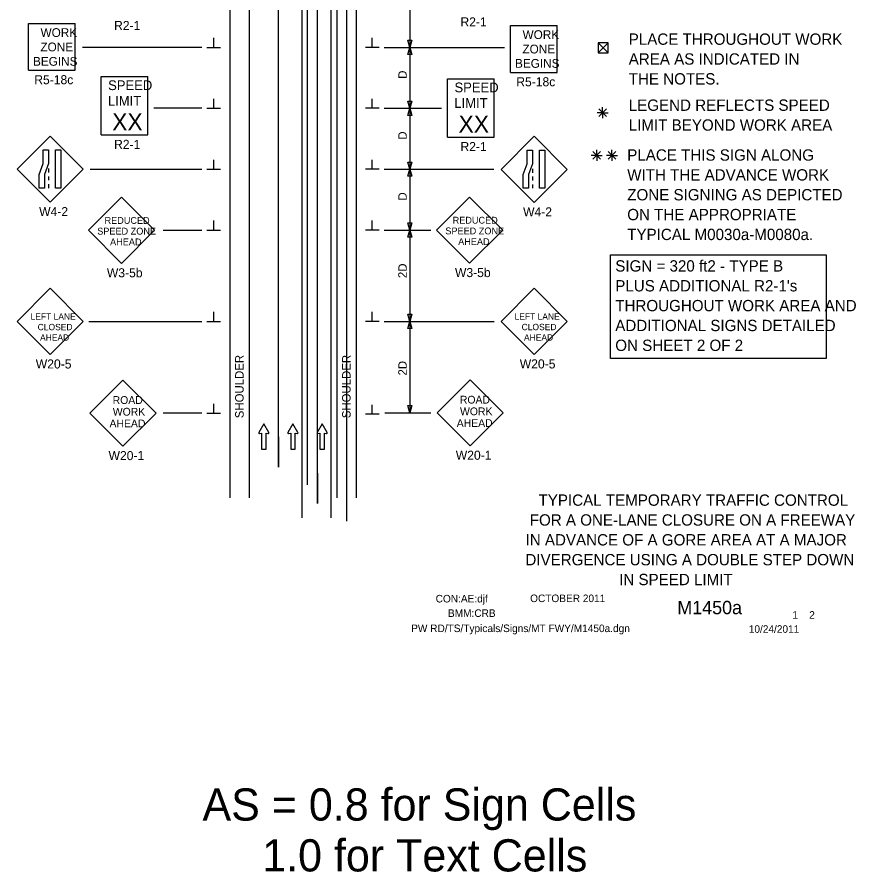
# Model space of a CAD drawing. Extents: x 16729 to 18464, y 5737 to 6974.
# Drawn here: x 16747 to 17436, y 5737 to 6439 of the extents above; entities that cross this region are included whole.
import ezdxf

# ---------------------------------------------------------------- set-up
doc = ezdxf.new("R2010")
doc.units = 0
for name, color, linetype in [('ALI_LEGAL_EX', 7, 'Continuous'), ('BORDER', 7, 'Continuous'), ('BORDER_SIGNAL_WO', 7, 'Continuous'), ('MT_SCRATCH_LEVEL_E', 7, 'Continuous'), ('PAVT_EDGE_EX', 7, 'Continuous'), ('TRAFFIC_SIGNS_PR', 7, 'Continuous'), ('TYPICAL_TEXT_DIMEN_EX', 7, 'Continuous'), ('TYPICAL_TEXT_DIMEN_PR', 7, 'Continuous')]:
    doc.layers.add(name, color=color, linetype=linetype)

msp = doc.modelspace()

# ---------------------------------------------------------------- linework, layer by layer
at = {"layer": 'ALI_LEGAL_EX'}
for p, q in [((16980.68, 6974.12), (16980.68, 6155.98)), ((17004.68, 6974.12), (17004.68, 6155.98)), ((16980.68, 6891.53), (16980.68, 6027.61)), ((17004.68, 6891.53), (17004.68, 6027.61)), ((16961.51, 6069.17), (16961.51, 6569.52)), ((16985.51, 6054.68), (16985.51, 6555.03)), ((16993.65, 6039.29), (16993.65, 6539.64)), ((17017.65, 6024.8), (17017.65, 6525.15))]:
    msp.add_line(p, q, dxfattribs=at)
for points in [[(16961.51, 6369.17), (16961.51, 6394.17)], [(16985.51, 6369.17), (16985.51, 6394.17)], [(16961.51, 6269.17), (16961.51, 6294.17)], [(16985.51, 6269.17), (16985.51, 6294.17)], [(16961.51, 6169.17), (16961.51, 6194.17)], [(16985.51, 6169.17), (16985.51, 6194.17)], [(16961.51, 6094.17), (16961.51, 6069.17)], [(16961.51, 6069.17), (16961.51, 6094.17)], [(16985.51, 6069.17), (16985.51, 6094.17)], [(16993.65, 6064.29), (16993.65, 6039.29)]]:
    msp.add_lwpolyline(points, dxfattribs=at)
at = {"layer": 'MT_SCRATCH_LEVEL_E'}
for p, q in [((16949.53, 6104.79), (16945.42, 6097.55)), ((16953.67, 6097.55), (16949.53, 6104.79)), ((16973.43, 6104.79), (16969.32, 6097.55)), ((16977.58, 6097.55), (16973.43, 6104.79)), ((16997.48, 6104.79), (16993.37, 6097.55)), ((17001.63, 6097.55), (16997.48, 6104.79)), ((16945.9, 6096.87), (16947.67, 6097.18)), ((16947.67, 6097.18), (16947.67, 6083.93)), ((16951.42, 6083.93), (16951.42, 6097.18)), ((16951.42, 6097.18), (16953.19, 6096.87)), ((16969.8, 6096.87), (16971.58, 6097.18)), ((16971.58, 6097.18), (16971.58, 6083.93)), ((16975.32, 6083.93), (16975.32, 6097.18)), ((16975.32, 6097.18), (16977.1, 6096.87)), ((16993.85, 6096.87), (16995.63, 6097.18)), ((16995.63, 6097.18), (16995.63, 6083.93)), ((16999.37, 6083.93), (16999.37, 6097.18)), ((16999.37, 6097.18), (17001.15, 6096.87)), ((16947.67, 6083.93), (16951.42, 6083.93)), ((16971.58, 6083.93), (16975.32, 6083.93)), ((16995.63, 6083.93), (16999.37, 6083.93))]:
    msp.add_line(p, q, dxfattribs=at)
for centre, start, end in [((16945.82, 6097.33), 150.42484, 279.96381), ((16953.26, 6097.33), 260.03619, 29.77312), ((16969.73, 6097.33), 150.42484, 279.96381), ((16977.17, 6097.33), 260.03619, 29.77312), ((16993.78, 6097.33), 150.42484, 279.96381), ((17001.22, 6097.33), 260.03619, 29.77312)]:
    msp.add_arc(centre, 0.463, start, end, dxfattribs=at)
at = {"layer": 'PAVT_EDGE_EX'}
for p, q in [((16921.51, 6569.52), (16921.51, 6043.9)), ((16937.51, 6569.52), (16937.51, 6043.9)), ((17009.51, 6569.52), (17009.51, 6043.9)), ((17025.51, 6569.52), (17025.51, 6043.9))]:
    msp.add_line(p, q, dxfattribs=at)
at = {"layer": 'TRAFFIC_SIGNS_PR'}
for p, q in [((16756.1, 6395.03), (16756.1, 6433.43)), ((16756.1, 6433.43), (16794.5, 6433.43)), ((16794.5, 6395.03), (16794.5, 6433.43)), ((17152.09, 6393.34), (17152.09, 6431.74)), ((17152.09, 6431.74), (17190.49, 6431.74)), ((17190.49, 6393.34), (17190.49, 6431.74)), ((16756.1, 6395.03), (16794.5, 6395.03)), ((16815.83, 6389.93), (16854.23, 6389.93)), ((16815.83, 6341.93), (16815.83, 6389.93)), ((16854.23, 6341.93), (16854.23, 6389.93)), ((17100.39, 6388.13), (17138.79, 6388.13)), ((17100.39, 6340.13), (17100.39, 6388.13)), ((17138.79, 6340.13), (17138.79, 6388.13)), ((17152.09, 6393.34), (17190.49, 6393.34)), ((16773.97, 6341.03), (16746.82, 6313.87)), ((16801.12, 6313.87), (16773.97, 6341.03)), ((16815.83, 6341.93), (16854.23, 6341.93)), ((17100.39, 6340.13), (17138.79, 6340.13)), ((17171.57, 6340.82), (17144.41, 6313.66)), ((17198.72, 6313.66), (17171.57, 6340.82)), ((16746.82, 6313.87), (16773.97, 6286.72)), ((16772.72, 6314.36), (16772.72, 6311.16)), ((16773.97, 6286.72), (16801.12, 6313.87)), ((17144.41, 6313.66), (17171.57, 6286.51)), ((17170.32, 6314.15), (17170.32, 6310.95)), ((17171.57, 6286.51), (17198.72, 6313.66)), ((16772.72, 6307.96), (16772.72, 6304.76)), ((17170.32, 6307.75), (17170.32, 6304.55)), ((16772.72, 6301.56), (16772.72, 6298.36)), ((17170.32, 6301.35), (17170.32, 6298.15)), ((16832.62, 6290.78), (16805.47, 6263.63)), ((16859.78, 6263.63), (16832.62, 6290.78)), ((17118.61, 6290.98), (17091.45, 6263.83)), ((17145.76, 6263.83), (17118.61, 6290.98)), ((16805.47, 6263.63), (16832.62, 6236.48)), ((16832.62, 6236.48), (16859.78, 6263.63)), ((17091.45, 6263.83), (17118.61, 6236.68)), ((17118.61, 6236.68), (17145.76, 6263.83)), ((16774.02, 6216), (16746.83, 6188.81)), ((16801.21, 6188.81), (16774.02, 6216)), ((17171.61, 6216.04), (17144.42, 6188.85)), ((17198.8, 6188.85), (17171.61, 6216.04)), ((16746.83, 6188.81), (16774.02, 6161.63)), ((16774.02, 6161.63), (16801.21, 6188.81)), ((17144.42, 6188.85), (17171.61, 6161.67)), ((17171.61, 6161.67), (17198.8, 6188.85)), ((16833.79, 6140.66), (16806.64, 6113.51)), ((16860.95, 6113.51), (16833.79, 6140.66)), ((17119.05, 6140.97), (17091.89, 6113.82)), ((17146.2, 6113.82), (17119.05, 6140.97)), ((16806.64, 6113.51), (16833.79, 6086.36)), ((16833.79, 6086.36), (16860.95, 6113.51)), ((17091.89, 6113.82), (17119.05, 6086.67)), ((17119.05, 6086.67), (17146.2, 6113.82))]:
    msp.add_line(p, q, dxfattribs=at)
for points in [[(16772.72, 6329.61), (16772.72, 6318.43), (16769.38, 6309.55), (16769.38, 6298.36), (16764.89, 6298.36), (16764.89, 6309.55), (16768.23, 6318.43), (16768.23, 6329.61)], [(16782.86, 6329.61), (16782.86, 6298.36), (16778.37, 6298.36), (16778.37, 6329.61)], [(17170.32, 6329.4), (17170.32, 6318.22), (17166.98, 6309.34), (17166.98, 6298.15), (17162.48, 6298.15), (17162.48, 6309.34), (17165.83, 6318.22), (17165.83, 6329.4)], [(17180.46, 6329.4), (17180.46, 6298.15), (17175.96, 6298.15), (17175.96, 6329.4)]]:
    msp.add_lwpolyline(points, close=True, dxfattribs=at)
at = {"layer": 'TYPICAL_TEXT_DIMEN_EX'}
msp.add_lwpolyline([(17234.19, 6243.59), (17411.46, 6243.59), (17411.46, 6158.27), (17234.19, 6158.27)], close=True, dxfattribs=at)
at = {"layer": 'TYPICAL_TEXT_DIMEN_PR'}
for p, q in [((17069.51, 6463.85), (17069.51, 6413.85)), ((16908.39, 6413.85), (16908.39, 6421.64)), ((17038.64, 6413.85), (17038.64, 6421.64)), ((17069.51, 6413.85), (17067.94, 6419.72)), ((17067.94, 6419.72), (17069.51, 6419.72)), ((17069.51, 6419.72), (17071.08, 6419.72)), ((17071.08, 6419.72), (17069.51, 6413.85)), ((17224.29, 6417.48), (17232.29, 6409.48)), ((17224.29, 6409.48), (17232.29, 6417.48)), ((16898.51, 6413.85), (16800.46, 6413.85)), ((16902.76, 6413.85), (16914.01, 6413.85)), ((17044.26, 6413.85), (17033.01, 6413.85)), ((17048.51, 6413.85), (17147.12, 6413.85)), ((17067.94, 6407.99), (17069.51, 6413.85)), ((17069.51, 6413.85), (17069.51, 6363.85)), ((17069.51, 6413.85), (17071.08, 6407.99)), ((17069.51, 6407.99), (17067.94, 6407.99)), ((17071.08, 6407.99), (17069.51, 6407.99)), ((16908.39, 6363.85), (16908.39, 6371.64)), ((17038.64, 6363.85), (17038.64, 6371.64)), ((17069.51, 6363.85), (17067.94, 6369.72)), ((17067.94, 6369.72), (17069.51, 6369.72)), ((17069.51, 6369.72), (17071.08, 6369.72)), ((17071.08, 6369.72), (17069.51, 6363.85)), ((16898.51, 6363.85), (16859.17, 6363.85)), ((16902.76, 6363.85), (16914.01, 6363.85)), ((17044.26, 6363.85), (17033.01, 6363.85)), ((17048.51, 6363.85), (17095.59, 6363.85)), ((17067.94, 6357.99), (17069.51, 6363.85)), ((17069.51, 6363.85), (17069.51, 6313.85)), ((17069.51, 6363.85), (17071.08, 6357.99)), ((17227.85, 6360.22), (17223.32, 6360.22)), ((17224.66, 6363.4), (17231.04, 6357.03)), ((17231.04, 6363.4), (17224.66, 6357.03)), ((17227.85, 6360.22), (17227.85, 6364.67)), ((17227.85, 6360.22), (17231.04, 6360.22)), ((17227.85, 6360.22), (17232.33, 6360.22)), ((17227.85, 6360.22), (17227.85, 6355.72)), ((17069.51, 6357.99), (17067.94, 6357.99)), ((17071.08, 6357.99), (17069.51, 6357.99)), ((17222.99, 6325.16), (17218.46, 6325.16)), ((17219.8, 6328.35), (17226.18, 6321.97)), ((17226.18, 6328.35), (17219.8, 6321.97)), ((17222.99, 6325.16), (17222.99, 6329.61)), ((17222.99, 6325.16), (17226.18, 6325.16)), ((17222.99, 6325.16), (17227.47, 6325.16)), ((17222.99, 6325.16), (17222.99, 6320.66)), ((17235.54, 6325.16), (17231.01, 6325.16)), ((17238.73, 6328.35), (17232.35, 6321.97)), ((17232.36, 6328.35), (17238.73, 6321.97)), ((17235.54, 6325.16), (17235.54, 6329.61)), ((17235.54, 6325.16), (17238.73, 6325.16)), ((17235.54, 6325.16), (17240.02, 6325.16)), ((17235.54, 6325.16), (17235.54, 6320.66)), ((16908.39, 6313.85), (16908.39, 6321.64)), ((17038.64, 6313.85), (17038.64, 6321.64)), ((17069.51, 6313.85), (17067.94, 6319.72)), ((17067.94, 6319.72), (17069.51, 6319.72)), ((17069.51, 6319.72), (17071.08, 6319.72)), ((17071.08, 6319.72), (17069.51, 6313.85)), ((16806.92, 6313.85), (16898.51, 6313.85)), ((16902.76, 6313.85), (16914.01, 6313.85)), ((17044.26, 6313.85), (17033.01, 6313.85)), ((17048.51, 6313.85), (17138.52, 6313.85)), ((17067.94, 6307.99), (17069.51, 6313.85)), ((17069.51, 6313.85), (17069.51, 6263.85)), ((17069.51, 6313.85), (17071.08, 6307.99)), ((17069.51, 6307.99), (17067.94, 6307.99)), ((17071.08, 6307.99), (17069.51, 6307.99)), ((16908.39, 6263.85), (16908.39, 6271.64)), ((17038.64, 6263.85), (17038.64, 6271.64)), ((17069.51, 6263.85), (17067.94, 6269.72)), ((17067.94, 6269.72), (17069.51, 6269.72)), ((17069.51, 6269.72), (17071.08, 6269.72)), ((17071.08, 6269.72), (17069.51, 6263.85)), ((16866.87, 6263.85), (16898.51, 6263.85)), ((16902.76, 6263.85), (16914.01, 6263.85)), ((17044.26, 6263.85), (17033.01, 6263.85)), ((17048.51, 6263.85), (17086.73, 6263.85)), ((17067.94, 6257.99), (17069.51, 6263.85)), ((17069.51, 6263.85), (17069.51, 6188.85)), ((17069.51, 6263.85), (17071.08, 6257.99)), ((17069.51, 6257.99), (17067.94, 6257.99)), ((17071.08, 6257.99), (17069.51, 6257.99)), ((16908.39, 6188.85), (16908.39, 6196.64)), ((17038.64, 6188.85), (17038.64, 6196.64)), ((17069.51, 6188.85), (17067.94, 6194.72)), ((17067.94, 6194.72), (17069.51, 6194.72)), ((17069.51, 6194.72), (17071.08, 6194.72)), ((17071.08, 6194.72), (17069.51, 6188.85)), ((16805.63, 6188.85), (16898.51, 6188.85)), ((16902.76, 6188.85), (16914.01, 6188.85)), ((17044.26, 6188.85), (17033.01, 6188.85)), ((17048.51, 6188.85), (17138.85, 6188.85)), ((17067.94, 6182.99), (17069.51, 6188.85)), ((17069.51, 6188.85), (17069.51, 6113.85)), ((17069.51, 6188.85), (17071.08, 6182.99)), ((17069.51, 6182.99), (17067.94, 6182.99)), ((17071.08, 6182.99), (17069.51, 6182.99)), ((16908.39, 6113.41), (16908.39, 6121.19)), ((17038.64, 6112.64), (17038.64, 6120.42)), ((17069.51, 6113.85), (17067.94, 6119.72)), ((17067.94, 6119.72), (17069.51, 6119.72)), ((17069.51, 6119.72), (17071.08, 6119.72)), ((17071.08, 6119.72), (17069.51, 6113.85)), ((16898.51, 6113.41), (16866.78, 6113.41)), ((16902.76, 6113.41), (16914.01, 6113.41)), ((17044.26, 6112.64), (17033.01, 6112.64)), ((17049.01, 6113.85), (17086.84, 6113.85))]:
    msp.add_line(p, q, dxfattribs=at)
msp.add_lwpolyline([(17224.29, 6417.48), (17224.29, 6409.48), (17232.29, 6409.48), (17232.29, 6417.48)], close=True, dxfattribs=at)

# ---------------------------------------------------------------- texts
at = {"layer": 'BORDER'}
for s, p in [('TYPICAL TEMPORARY TRAFFIC CONTROL', (17175.21, 6037.44)), ('FOR A ONE-LANE CLOSURE ON A FREEWAY', (17167.99, 6021.14)), ('IN ADVANCE OF A GORE AREA AT A MAJOR', (17164.54, 6004.84)), ('DIVERGENCE USING A DOUBLE STEP DOWN ', (17164.42, 5988.54)), ('IN SPEED LIMIT', (17241.42, 5972.24))]:
    msp.add_text(s, height=9.3, dxfattribs=at).set_placement(p)
at = {"layer": 'BORDER_SIGNAL_WO'}
for s, height, p in [('CON:AE:djf  ', 6.2, (17090.69, 5958.06)), ('    OCTOBER 2011    ', 6.2, (17159.08, 5958.34)), ('    M1450a   ', 11, (17272.86, 5948.38)), ('BMM:CRB   ', 6.2, (17100.81, 5946.17)), (' 1    2 ', 6.2, (17381.45, 5944.7)), ('PW RD/TS/Typicals/Signs/MT FWY/M1450a.dgn      ', 6.2, (17070.55, 5933.71)), ('10/24/2011    ', 6.2, (17347.93, 5933.13)), ('AS = 0.8 for Sign Cells', 26.4241, (16899.12, 5778.94)), ('     1.0 for Text Cells', 26.4241, (16899.12, 5737.16))]:
    msp.add_text(s, height=height, dxfattribs=at).set_placement(p)
at = {"layer": 'TRAFFIC_SIGNS_PR'}
for s, height, p in [('R2-1', 7.44, (17111.07, 6431.07)), ('R2-1', 7.44, (16826.51, 6428.11)), ('WORK', 7.217, (16766.1, 6422.4)), ('WORK', 7.217, (17162.09, 6420.71)), ('ZONE', 7.217, (16765.98, 6410.59)), ('ZONE', 7.217, (17161.97, 6408.9)), ('BEGINS', 7.217, (16759.91, 6398.78)), ('BEGINS', 7.217, (17155.9, 6397.09)), ('R5-18c', 7.44, (16760.91, 6383.59)), ('R5-18c', 7.44, (17156.9, 6381.9)), ('SPEED', 8, (16821.6, 6378.79)), ('SPEED', 8, (17106.16, 6376.99)), ('LIMIT', 8, (16821.44, 6365.99)), ('LIMIT', 8, (17106, 6364.19)), ('XX', 14.031, (16824.94, 6345.69)), ('XX', 14.031, (17109.5, 6343.88)), ('R2-1', 7.44, (16826.51, 6330.49)), ('R2-1', 7.44, (17111.07, 6328.69)), ('W4-2', 7.44, (16764.93, 6275.28)), ('W4-2', 7.44, (17162.52, 6275.07)), ('REDUCED', 5.6, (16818.68, 6268.94)), ('REDUCED', 5.6, (17104.67, 6269.14)), ('SPEED ZONE', 5.6, (16812.67, 6260.14)), ('SPEED ZONE', 5.6, (17098.66, 6260.34)), ('AHEAD', 5.6, (16823.23, 6251.34)), ('AHEAD', 5.6, (17109.22, 6251.54)), ('W3-5b', 7.44, (16820.58, 6225.04)), ('W3-5b', 7.44, (17106.56, 6225.24)), ('LEFT LANE', 5.206, (16757.88, 6190.21)), ('LEFT LANE', 5.206, (17155.47, 6190.25)), ('CLOSED', 5.206, (16763.72, 6181.6)), ('CLOSED', 5.206, (17161.31, 6181.64)), ('AHEAD', 5.206, (16765.67, 6172.99)), ('AHEAD', 5.206, (17163.26, 6173.03)), ('W20-5', 7.449, (16762.18, 6150.17)), ('W20-5', 7.449, (17159.77, 6150.21)), ('ROAD', 6.4, (16825.34, 6121.05)), ('ROAD', 6.4, (17110.59, 6121.36)), ('WORK', 6.4, (16825.45, 6111.45)), ('WORK', 6.4, (17110.7, 6111.76)), ('AHEAD', 6.4, (16822.76, 6101.85)), ('AHEAD', 6.4, (17108.01, 6102.15)), ('W20-1', 7.44, (16821.96, 6074.92)), ('W20-1', 7.44, (17107.22, 6075.23))]:
    msp.add_text(s, height=height, dxfattribs=at).set_placement(p)
at = {"layer": 'TYPICAL_TEXT_DIMEN_EX'}
for s, p in [('PLACE THROUGHOUT WORK', (17249.3, 6415.98)), ('AREA AS INDICATED IN', (17249.3, 6399.68)), ('THE NOTES.', (17249.3, 6383.38)), ('LEGEND REFLECTS SPEED', (17249.3, 6361.75)), ('LIMIT BEYOND WORK AREA', (17249.3, 6345.45)), ('PLACE THIS SIGN ALONG', (17248.08, 6320.83)), ('WITH THE ADVANCE WORK', (17248.08, 6304.53)), ('ZONE SIGNING AS DEPICTED', (17248.08, 6288.23)), ('ON THE APPROPRIATE', (17248.08, 6271.93)), ('TYPICAL M0030a-M0080a.', (17248.08, 6255.63)), ('SIGN = 320 ft2 - TYPE B', (17238.24, 6229.76)), ("PLUS ADDITIONAL R2-1's", (17238.24, 6213.46)), ('THROUGHOUT WORK AREA AND', (17238.24, 6197.16)), ('ADDITIONAL SIGNS DETAILED', (17238.24, 6180.86)), ('ON SHEET 2 OF 2', (17238.24, 6164.56))]:
    msp.add_text(s, height=9.3, dxfattribs=at).set_placement(p)
at = {"layer": 'TYPICAL_TEXT_DIMEN_PR'}
for s, p in [('D', (17066.95, 6388.07)), ('D', (17066.95, 6338.07)), ('D', (17066.95, 6288.07)), ('2D', (17066.95, 6224.41)), ('SHOULDER', (16932.95, 6109.34)), ('SHOULDER', (17020.81, 6109.34)), ('2D', (17066.95, 6144.43))]:
    msp.add_text(s, height=7, rotation=90, dxfattribs=at).set_placement(p)

doc.saveas('drawing.dxf')
